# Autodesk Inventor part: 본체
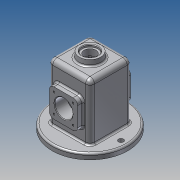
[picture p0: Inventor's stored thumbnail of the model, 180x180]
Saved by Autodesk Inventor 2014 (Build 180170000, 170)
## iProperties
Created: 2021-08
Part Number: 본체
Material: 알루미늄 6061
Document SubType Name: Modeling
Designer: kb542-04
Density: 2.71 g/cm^3
Appearance: 알루미늄 - 평지
Mass: 812.503 g
Surface Area: 933.129 cm^2
Volume: 299.816 cm^3
Author: kb542-04
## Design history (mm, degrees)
sketch "스케치2"
  geometry: C1 r 67 at (0, 0); 1 further point
  constraints: 1 centre point, 1 coincident
  dimensions: "d0" = 134 diameter of C1
extrude "돌출1" new body sketch "스케치2" distance "d1" = 10; taper "d2" = 0 deg
fillet "모깎기1" dims "d3" = 3
sketch "스케치3"
  geometry: L1 (37, -37)-(-37, -37); L2 (-37, -37)-(-37, 37); L3 (-37, 37)-(37, 37); L4 (37, 37)-(37, -37); L5 (37, -37)-(-37, 37); L6 (-37, -37)-(37, 37); 1 further point
  constraints: 12 end point, 2 midpoint, 2 parallel, 1 horizontal, 1 perpendicular
  dimensions: "d4" = 74 distance of L2.end L3.end; "d5" = 74 distance of L1.end L2.end
extrude "돌출2" join sketch "스케치3" distance "d6" = 100; taper "d7" = 0 deg
fillet "모깎기2" dims "d8" = 8
fillet "모깎기3" dims "d9" = 3
fillet "모깎기4" dims "d10" = 8
sketch "스케치7"
  geometry: C1 r 20 at (0, 0); 1 further point
  constraints: 1 centre point, 1 coincident
  dimensions: "d32" = 40 diameter of C1
extrude "돌출5" join sketch "스케치7" distance "d33" = 10; taper "d34" = -6 deg
sketch "스케치8"
  geometry: C1 r 14 at (0, 0); 1 further point
  constraints: 1 centre point, 1 coincident
  dimensions: "d35" = 28 diameter of C1
extrude "돌출6" cut sketch "스케치8" distance "d36" = 4; taper "d37" = 0 deg
sketch "스케치9"
  geometry: C1 r 10.5 at (0, 0); 1 further point
  constraints: 1 centre point, 1 coincident
  dimensions: "d38" = 21 diameter of C1
extrude "돌출7" cut sketch "스케치9" stored distance "d39" = 4; taper "d40" = 0 deg
sketch "스케치13"
  geometry: L1 (54, 17)-(4, 17); L2 (4, 17)-(4, 67); L3 (4, 67)-(54, 67); L4 (54, 67)-(54, 17); L5 (54, 17)-(4, 67); L6 (4, 17)-(54, 67); L7 (-38, -13)-(96, -13) reference; 4 further points
  constraints: 12 end point, 4 midpoint, 2 parallel, 1 horizontal, 1 perpendicular, 1 vertical alignment
  dimensions: "d47" = 50 distance of L2.end L3.end; "d48" = 50 distance of L1.end L2.end; "d49" = 55 distance from line of L7 point (29, 42)
extrude "돌출9" join sketch "스케치13" distance "d50" = 10; taper "d51" = 0 deg
fillet "모깎기9" dims "d56" = 8
fillet "모깎기10" dims "d57" = 3
sketch "스케치15"
  geometry: L1 (32, -32)-(-32, -32); L2 (-32, -32)-(-32, 32); L3 (-32, 32)-(32, 32); L4 (32, 32)-(32, -32); L5 (32, -32)-(-32, 32); L6 (-32, -32)-(32, 32); 1 further point
  constraints: 12 end point, 2 midpoint, 2 parallel, 1 horizontal, 1 perpendicular
  dimensions: "d58" = 64 distance of L2.end L3.end; "d59" = 64 distance of L1.end L2.end
extrude "돌출10" cut sketch "스케치15" distance "d60" = 105; taper "d61" = 0 deg
sketch "스케치16"
  geometry: L1 (0, -32)-(105, -32) reference; L2 (102, -37)-(13, -37) reference; L3 (79.856, -50.567)-(55, -50.567); L4 (55, -50.567)-(55, -15.891); L5 (55, -15.891)-(65.107, -15.891); L6 (65.107, -15.891)-(79.856, -32); L7 (79.856, -50.567)-(79.856, -32); L8 (0, 67)-(0, -67) reference; L9 (80, 47)-(80, 40) reference; L10 (0, 32)-(105, 32) reference; L11 (83, 37)-(83, 32); L12 (83, 32)-(80.452, 25); L13 (80.452, 25)-(55, 25); L14 (55, 25)-(55, 32); L15 (83, 32)-(55, 32); A1 r 3 centre (83, 40) between (80, 40) and (83, 37) reference; 1 further point
  constraints: 20 end point, 4 perpendicular, 3 point on line, 2 parallel
  dimensions: "d62" = 55 distance between parallel lines of L8 L4; "d63" = 25 distance between parallel lines of L9 L14; "d64" = 110 deg angle of L10 L12; "d65" = 7 distance between parallel lines of L15 L13
revolve "회전2" sketch "스케치16" stored, may be unused: angle "d66" = 90 deg
sketch "스케치17"
  geometry: L1 (-38, -13)-(96, -13) reference; C1 r 16 at (29, 42); 2 further points
  constraints: 1 centre point, 1 midpoint, 1 vertical alignment
  dimensions: "d67" = 32 diameter of C1; "d68" = 55 distance from line of L1 C1.centre
extrude "돌출11" cut sketch "스케치17" stored distance "d69" = 105; taper "d70" = 0 deg
fillet "모깎기11" dims "d71" = 3
fillet "모깎기12" dims "d72" = 3
chamfer "모따기1" distance "d73" = 1; stored, may be unused: second distance "d74" = 2, angle "d75" = 45 deg
fillet "모깎기13" dims "d76" = 8
fillet "모깎기14" dims "d77" = 3
sketch "스케치19"
  geometry: L1 (46, 25)-(12, 25); L2 (12, 25)-(12, 59); L3 (12, 59)-(46, 59); L4 (46, 59)-(46, 25); L5 (46, 25)-(12, 59); L6 (12, 25)-(46, 59); L7 (-38, -13)-(96, -13) reference; 7 further points
  constraints: 12 end point, 4 coincident, 3 midpoint, 2 parallel, 1 horizontal, 1 perpendicular, 1 vertical alignment
  dimensions: "d78" = 34 distance of L2.end L3.end; "d79" = 34 distance of L1.end L2.end; "d80" = 55 distance from line of L7 point (29, 42)
hole "구멍2" sketch "스케치19" at (12, 59), (46, 59), (46, 25), (12, 25) diameter "d81" = 3.242; stored, may be unused: countersink angle "d85" = 90 deg, drill point angle "d87" = 118 deg; dims "d82" = 8, "d83" = 4, "d84" = 2, "d86" = 10
sketch "스케치20"
  geometry: C1 r 4.5 at (-55, 0); C2 r 4.5 at (55, 0); C3 r 55 at (0, 0); 1 further point
  constraints: 3 centre point, 2 horizontal alignment, 1 coincident
  dimensions: "d90" = 9 diameter of C1; "d91" = 9 diameter of C2; "d92" = 110 diameter of C3
extrude "돌출12" cut sketch "스케치20" distance "d93" = 10; taper "d94" = 0 deg
sketch "스케치21"
  geometry: L1 (-8, 89)-(-8, 0) reference; L2 (10.051, 107)-(47.949, 107) reference; 2 further points
  constraints: 1 other
  dimensions: "d95" = 37 distance from line of point (29, 79) L1; "d96" = 28 distance from line of point (29, 79) L2
feature "엠보싱1" sketch "스케치21" dims "d1" = 10, "d97" = 0.5, "d98" = 0
fillet "모깎기15" dims "d99" = 3
node "솔리드1"
mirror "대칭4"
mirror "대칭5"
